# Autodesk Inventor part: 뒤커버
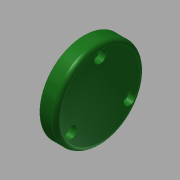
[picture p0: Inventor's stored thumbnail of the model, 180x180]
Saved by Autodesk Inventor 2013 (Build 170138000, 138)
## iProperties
Created: 2015-11
Part Number: 뒤커버
Material: 알루미늄 6061
Document SubType Name: Modeling
Designer: mduedu
Density: 1 g/cm^3
Author: mduedu
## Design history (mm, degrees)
sketch "스케치5"
  geometry: C1 r 30 at (0, 0); 2 further points
  constraints: 2 coincident, 1 centre point
  dimensions: "d66" = 60 diameter of C1
extrude "돌출2" new body sketch "스케치5" distance "d67" = 11; taper "d68" = 0 deg
sketch "스케치6"
  geometry: C1 r 16 at (0, 0); 1 further point
  constraints: 1 centre point, 1 coincident
  dimensions: "d69" = 32 diameter of C1
extrude "돌출3" join sketch "스케치6" distance "d70" = 3; taper "d71" = 0 deg
hole "구멍5" diameter "d74" = 25; stored, may be unused: countersink angle "d78" = 90 deg, drill point angle "d80" = 0 deg; dims "d72" = 10, "d73" = 10, "d75" = 6, "d76" = 4, "d77" = 2, "d79" = 10
fillet "모깎기8" dims "d82" = 3
fillet "모깎기9" dims "d83" = 3
fillet "모깎기10" dims "d84" = 0.3
sketch "스케치7" dims "d85" = 46
  geometry: 3 further points
  constraints: 2 vertical alignment, 1 coincident, 2 other
hole "구멍6" sketch "스케치7" at (0, 23) diameter "d86" = 4.5; stored, may be unused: countersink angle "d90" = 90 deg, drill point angle "d92" = 0 deg; dims "d87" = 6, "d88" = 8, "d89" = 4.6, "d91" = 10
node "솔리드2"
pattern_circular "원형 패턴3" dims angle "d94" = 360 deg
